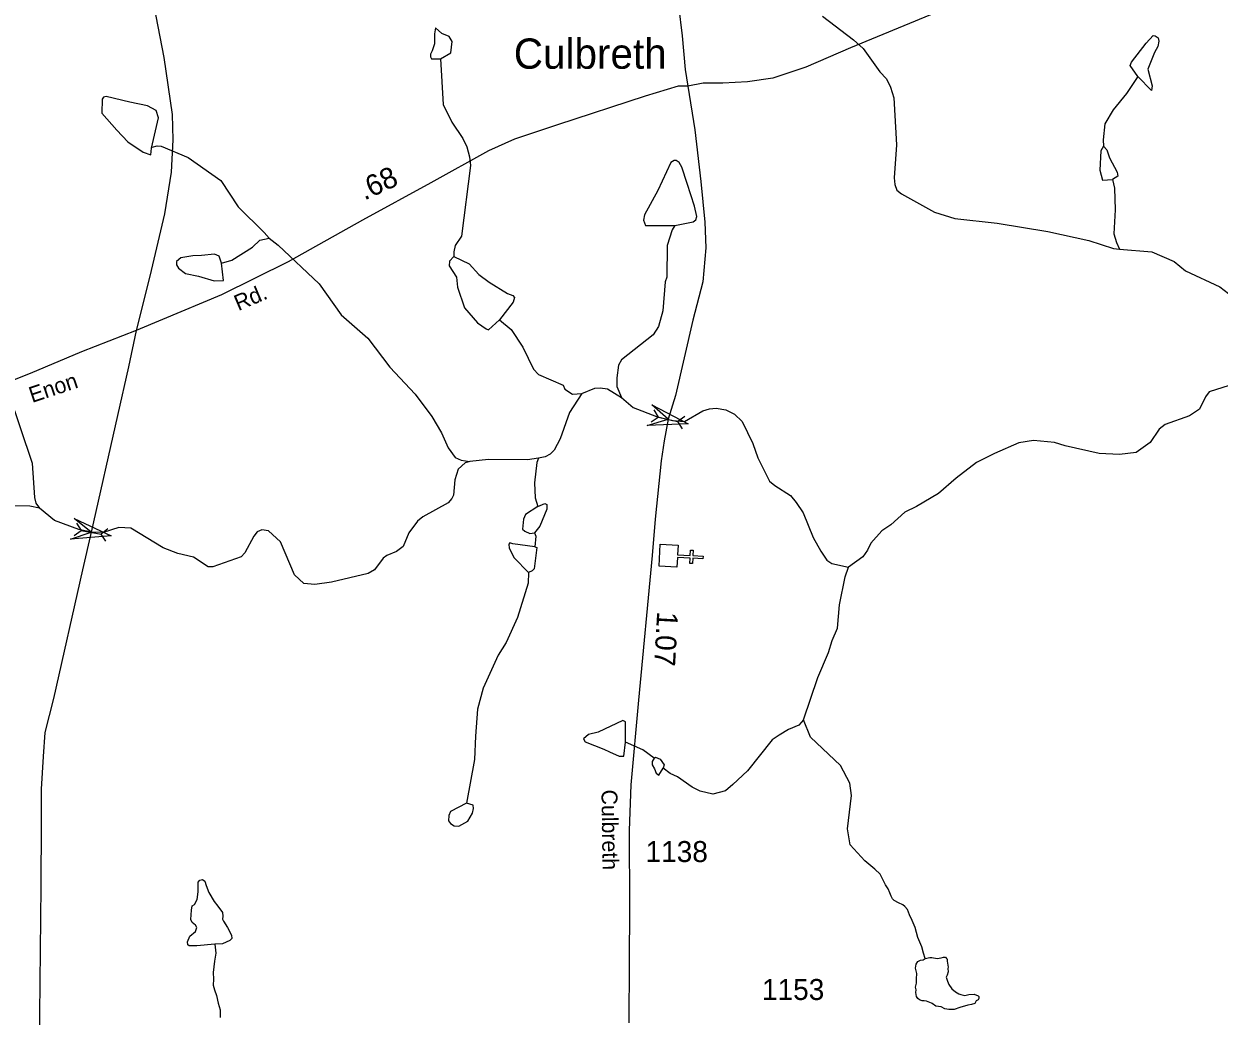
# Model space of a CAD drawing. Extents: x 2056842 to 2160602, y 826753 to 1016856.
# Drawn here: x 2076563 to 2083693, y 909292 to 915209 of the extents above; entities that cross this region are included whole.
import ezdxf

# ---------------------------------------------------------------- set-up
doc = ezdxf.new("R2010")
doc.units = 0
for name, color, linetype in [('Exist Civil Demographics City Label', 7, 'Continuous'), ('Exist Cultural Church CELL', 7, 'Continuous'), ('Exist Hydrographic Creek Single Shore', 7, 'Continuous'), ('Exist Hydrographic Misc Water Feature', 7, 'Continuous'), ('Exist Road Secondary Mileage Hundredths English Label', 7, 'Continuous'), ('Exist Road Secondary Structure Pipe Attributed CELL', 7, 'Continuous'), ('Exist Road Secondary Structure Pipe CELL', 7, 'Continuous'), ('Exist Road Secondary Structure Standard Bridge Attributed CELL', 7, 'Continuous'), ('Exist Road Secondary Type 51 Attributed', 7, 'Continuous'), ('Exist Road Secondary Type 51 Label', 7, 'Continuous'), ('Exist Road Secondary Type 51 Number Label', 7, 'Continuous')]:
    doc.layers.add(name, color=color, linetype=linetype)

msp = doc.modelspace()

# ---------------------------------------------------------------- linework, layer by layer
at = {"layer": 'Exist Cultural Church CELL'}
msp.add_lwpolyline([(2080465.2, 912100.6), (2080462, 912043.7), (2080538.1, 912039.4), (2080539.9, 912071.3), (2080555.8, 912070.4), (2080554, 912038.5), (2080614, 912035.1), (2080613.1, 912019.1), (2080553.1, 912022.5), (2080551.3, 911990.5), (2080535.3, 911991.4), (2080537.1, 912023.4), (2080461.1, 912027.7), (2080457.7, 911970.2), (2080351.4, 911976.2), (2080358.9, 912106.6)], close=True, dxfattribs=at)
at = {"layer": 'Exist Hydrographic Creek Single Shore'}
for points in [[(2081327.5, 915255.7), (2081512, 915114.1), (2081568.3, 915062.4), (2081668.8, 914922.8), (2081708.9, 914881), (2081732.9, 914832.9), (2081751.2, 914768.9), (2081768.1, 914488.9), (2081754.8, 914291), (2081758.9, 914250.9), (2081771, 914217.2), (2081797.1, 914195), (2081995.3, 914085.9), (2082115.3, 914048.3), (2082369.3, 914021), (2082671.5, 913971.8), (2082915.8, 913916.9), (2083061.8, 913869.2), (2083097.8, 913865.2)], [(2079046.9, 915000.5), (2079063.7, 914728.6), (2079116.2, 914622.8), (2079180.3, 914525), (2079204.5, 914477), (2079220.7, 914417.2), (2079226.9, 914365.2), (2079172.1, 913943), (2079134.4, 913886.9), (2079126.4, 913850.9), (2079126.6, 913822.9)], [(2077327.9, 914474.5), (2077356.6, 914481.2), (2077380.5, 914481), (2077542.5, 914411.7), (2077736.9, 914276.1), (2077841.6, 914118.8), (2077995.9, 913965.3), (2078026.1, 913931.2)], [(2078026.1, 913931.2), (2078080.3, 913889.4), (2078324.9, 913658.2), (2078455.6, 913474.7), (2078613.9, 913335.3), (2078746.4, 913161.6), (2078897, 913001.9), (2078995.3, 912868.3), (2079053.7, 912770.6), (2079094.1, 912680.5), (2079136.2, 912622.9), (2079170.4, 912606.8), (2079222.4, 912599.1)], [(2083097.8, 913865.2), (2083292.1, 913850), (2083424.1, 913792.5), (2083492.2, 913736.6), (2083696.6, 913641.1), (2083748.6, 913601.3), (2083768.8, 913515.3), (2083759.1, 913473.5), (2083767.3, 913443.5), (2083815.3, 913401.4), (2083863.5, 913381.7), (2083879.3, 913383.7), (2083919.2, 913440), (2083923.1, 913472.1), (2083937, 913494.1), (2083951, 913504)], [(2079126.6, 913822.9), (2079100.6, 913794.8), (2079098.7, 913766.8), (2079143, 913699), (2079149.2, 913638.9), (2079191.4, 913515.1), (2079267.9, 913427.4), (2079320, 913391.5), (2079333.9, 913385.5), (2079399.8, 913443.8)], [(2079126.6, 913822.9), (2079218.7, 913779.1), (2079276.9, 913715.4), (2079339.1, 913669.5)], [(2079339.1, 913669.5), (2079447.1, 913602), (2079479.1, 913590), (2079489.4, 913578.1), (2079481.4, 913550), (2079399.8, 913443.8)], [(2079399.8, 913443.8), (2079469.9, 913385.9), (2079538.2, 913282.2), (2079602.6, 913150.4), (2079632.7, 913118.6), (2079778.9, 913055), (2079788.9, 913031), (2079835.1, 913001.2), (2079891.1, 913005.4)], [(2075594.1, 913381.4), (2075654.3, 913311.9), (2075716.4, 913282.1), (2075836.3, 913256.3), (2075970.5, 913242.7), (2076108.7, 913213.2), (2076294.8, 913151.6), (2076403, 913086), (2076471.3, 913008.2), (2076612.6, 912588.9), (2076625.1, 912384.8), (2076633.3, 912350.9), (2076655.3, 912320.9)], [(2079891, 913005.3), (2079817.4, 912891), (2079761.7, 912734.6), (2079726.1, 912666.8), (2079702, 912642.7), (2079672.1, 912626.6), (2079632.3, 912618.5)], [(2079891, 913005.3), (2079968.8, 913037.5), (2080000.9, 913039.4), (2080044.8, 913033.6), (2080127.1, 912982)], [(2083752.3, 913053.3), (2083632.4, 913015.1), (2083610.5, 912985), (2083574.8, 912911), (2083515, 912872.8), (2083371.1, 912820.3), (2083335.1, 912792.2), (2083281.6, 912711.9), (2083197.7, 912653.6), (2083097.7, 912641.3), (2082977.8, 912647), (2082773.6, 912692.3), (2082709.7, 912712), (2082585.6, 912725.7), (2082497.7, 912711.4), (2082351.7, 912646.9), (2082245.9, 912592.6), (2082124.2, 912500.3), (2082018.6, 912408), (2081886.8, 912331.7), (2081816.8, 912297.3), (2081735.2, 912220.9), (2081681.3, 912185), (2081615.5, 912112.8), (2081595.6, 912070.6), (2081567.8, 912030.5), (2081481.9, 911968.3)], [(2080127.1, 912982), (2080197, 912922.2), (2080337.3, 912868.7), (2080431.4, 912844.8), (2080503.4, 912839), (2080613.3, 912901.4), (2080653.3, 912913.7), (2080693.1, 912917.8), (2080749.3, 912907.8), (2080801.3, 912882.1), (2080847.3, 912838.2), (2080911.8, 912706.6), (2080939.9, 912620.7), (2081010.5, 912482.7), (2081042.5, 912456.8), (2081134.8, 912397.1), (2081169, 912355.4), (2081211, 912293.5), (2081271.6, 912145.6), (2081315.9, 912063.9), (2081351.9, 912012), (2081382, 911992), (2081481.9, 911968.3)], [(2079222.4, 912599.1), (2079194.3, 912590.9), (2079152.5, 912553), (2079132.5, 912490.7), (2079125, 912398.7), (2079115.1, 912378.9), (2079092.9, 912352.8), (2078943.2, 912270.2), (2078911.5, 912244), (2078859.5, 912173.8), (2078826, 912091.8), (2078786, 912061.8), (2078728.1, 912039.4), (2078706.1, 912023.5), (2078654.5, 911953.3), (2078616.3, 911931.1), (2078396.7, 911880.6), (2078298.6, 911866.2), (2078232.8, 911872.1), (2078176.4, 911923.8), (2078093.9, 912119.5), (2078021.7, 912185.3), (2077981.5, 912191), (2077953.7, 912179.1), (2077933.8, 912154.9), (2077880.2, 912055), (2077858.1, 912030.8), (2077690.5, 911970.3), (2077662.3, 911972.2), (2077574.2, 912029.8), (2077480.2, 912051.5), (2077393.9, 912085.4), (2077200.1, 912202), (2077128.7, 912206.1), (2077035.8, 912176.4), (2076963.1, 912177.8), (2076889.9, 912193.6), (2076745.6, 912247.1), (2076655.3, 912320.9)], [(2079632.3, 912618.5), (2079566.1, 912610.1), (2079334.2, 912611.6), (2079222.4, 912599.1)], [(2076655.3, 912320.9), (2076597.4, 912332.9), (2076445.2, 912334.4), (2076309.4, 912286), (2076197.7, 912215.5), (2076167.8, 912183.3), (2076110.1, 912073.3), (2076096.3, 912029.3), (2076084.6, 911969.1), (2076082.9, 911857.3), (2076063, 911797), (2076043.1, 911773.1), (2076011.3, 911755.1), (2075875.4, 911720.5), (2075845.4, 911698.4)], [(2081213, 911059.6), (2081298.3, 911311.9), (2081361.9, 911460.1), (2081383.6, 911532.2), (2081415.4, 911606.2), (2081428.9, 911744.3), (2081462.4, 911912.3), (2081482.3, 911968.4)], [(2081213, 911059.6), (2081185.1, 911027.6), (2081123.4, 911001.4), (2081067.4, 910967.3), (2081025.4, 910939.1), (2080880, 910754.6), (2080792.3, 910672.4), (2080748.4, 910636.2), (2080672.5, 910616), (2080596.4, 910633.7), (2080548.5, 910657.6), (2080462.1, 910719.3), (2080418.2, 910739.1), (2080376, 910771)], [(2081701.9, 910074.5), (2081670.3, 910138.6), (2081639.1, 910168.9), (2081579.7, 910216.9), (2081491.5, 910312.6), (2081475.1, 910408.6), (2081500.5, 910606.6), (2081490.3, 910680.6), (2081433.9, 910786.4), (2081255.5, 910955.8), (2081213, 911059.6)], [(2081939.1, 909635.3), (2081928.9, 909667.2), (2081919, 909705.3), (2081894.6, 909761.1), (2081878.6, 909821.1), (2081862.4, 909861), (2081846.4, 909894.9), (2081834.1, 909926.9), (2081818.1, 909944.9), (2081806, 909954.8), (2081780, 909966.8), (2081754.2, 909980.6), (2081744.1, 909990.7), (2081735.9, 910006.6), (2081727.9, 910026.6), (2081717.9, 910050.6), (2081709.9, 910062.6), (2081701.9, 910074.5)]]:
    msp.add_lwpolyline(points, dxfattribs=at)
at = {"layer": 'Exist Hydrographic Misc Water Feature'}
for p, q in [((2079629.2, 912330.5), (2079555.4, 912284.3)), ((2079609.9, 912090.5), (2079479.9, 912108.1))]:
    msp.add_line(p, q, dxfattribs=at)
for points in [[(2079116.4, 915104.8), (2079098.5, 915134.7), (2079056.3, 915152.6), (2079018.2, 915186.4), (2079012.4, 915150.4), (2079012.6, 915090.4)], [(2083258.2, 915093.9), (2083300, 915140), (2083312.1, 915138), (2083328.1, 915126), (2083332.2, 915106), (2083326.1, 915074), (2083306.4, 915038.1)], [(2079012.6, 915090.4), (2078998.7, 915048.4), (2078988.6, 915028.4), (2078988.8, 915012.4), (2078994.8, 915000.4), (2079046.9, 915000.5)], [(2079046.9, 915000.5), (2079108.8, 915036.7), (2079116.4, 915104.8)], [(2083206.8, 914895.6), (2083162.5, 914961.6), (2083170.5, 914981.6), (2083258.2, 915093.9)], [(2083306.4, 915038.1), (2083266.6, 914939.8), (2083292.9, 914840), (2083289, 914812), (2083206.8, 914895.6)], [(2083206.8, 914895.6), (2083141.1, 914793.5), (2083061.4, 914697.3), (2083011.7, 914613.1), (2083000.1, 914517), (2083002.1, 914481.1)], [(2077193.8, 914742.7), (2077053.8, 914776.2), (2077037.8, 914772.2), (2077029.8, 914760.2), (2077028.1, 914676.1), (2077116.3, 914576.5)], [(2077322.8, 914469.1), (2077366, 914649.3), (2077351.9, 914693.2), (2077299.8, 914721), (2077193.8, 914742.7)], [(2077116.3, 914576.5), (2077182.5, 914506.7), (2077274.8, 914444.9), (2077318.9, 914429), (2077322.8, 914469.1)], [(2083002.1, 914481.1), (2082986.1, 914453), (2082980.6, 914337.1)], [(2083002.1, 914481.1), (2083022.2, 914459.2), (2083038.4, 914411.2), (2083084.5, 914325.4), (2083088.6, 914301.4), (2083056.9, 914281.3)], [(2080519.1, 914257.3), (2080486.7, 914355.1), (2080470.7, 914383.1), (2080454.5, 914395), (2080442.6, 914395), (2080422.8, 914382.9), (2080345.2, 914216.7)], [(2082980.6, 914337.1), (2082996.8, 914277.1), (2083056.9, 914281.3)], [(2083056.9, 914281.3), (2083069, 914229.3), (2083073.3, 914101.4), (2083063.8, 913957.3), (2083080, 913905.3), (2083098.1, 913865.5)], [(2080345.2, 914216.7), (2080265.7, 914070.4), (2080259.7, 914038.4), (2080269.8, 914006.5), (2080445.7, 914007.1)], [(2080445.7, 914007.1), (2080555.8, 914029.4), (2080571.6, 914041.5), (2080577.8, 914061.5), (2080563.4, 914121.4), (2080519.1, 914257.3)], [(2080445.7, 914007.1), (2080429.9, 913981), (2080400.2, 913886.9), (2080398.8, 913698.9), (2080388.9, 913670.9), (2080373.5, 913498.8), (2080347.9, 913404.7), (2080315.9, 913354.7), (2080128.5, 913206), (2080110.5, 913174), (2080098.8, 913098), (2080099, 913046), (2080127.1, 912982.1)], [(2077740.9, 913782.5), (2077802.8, 913800.7), (2077926.5, 913877), (2077970.3, 913919.2), (2078026.3, 913931.4)], [(2077570.7, 913826), (2077498.7, 913813.7), (2077472.9, 913791.6), (2077472.9, 913771.7), (2077485, 913751.7), (2077527, 913719.8), (2077605.1, 913704)], [(2077740.9, 913782.5), (2077726.7, 913824.5), (2077698.6, 913836.3), (2077622.8, 913828.1), (2077570.7, 913826)], [(2077605.1, 913704), (2077697, 913676.3), (2077753.2, 913678.6), (2077740.9, 913782.5)], [(2079632.3, 912618.5), (2079622.4, 912594.5), (2079608.9, 912472.4), (2079613, 912382.5), (2079629.2, 912330.5)], [(2079629.2, 912330.5), (2079669.2, 912348.7), (2079681.3, 912342.7), (2079681.3, 912314.8), (2079639.7, 912214.6), (2079607.7, 912174.5)], [(2079555.4, 912284.3), (2079543.5, 912256.3), (2079537.8, 912196.3), (2079551.7, 912184.3), (2079579.8, 912170.4), (2079607.7, 912174.5)], [(2079607.7, 912174.5), (2079615.9, 912154.5), (2079609.9, 912090.5)], [(2079479.9, 912108.1), (2079461.9, 912114), (2079455.9, 912106), (2079458, 912082), (2079486.3, 912024.2), (2079572.4, 911938.4)], [(2079609.9, 912090.5), (2079622, 912086.5), (2079606.2, 911958.6), (2079594.6, 911946.5), (2079572.4, 911938.4)], [(2079572.4, 911938.4), (2079570.8, 911874.4), (2079507.4, 911668.2), (2079439.9, 911520.1), (2079392.2, 911443.9), (2079302.8, 911247.6), (2079269.1, 911121.6), (2079255.6, 910961.4), (2079250.1, 910821.5), (2079202.9, 910561.4)], [(2080151.7, 910926.3), (2080151.3, 911046.3), (2080135.3, 911054.3), (2079987.4, 910985.8)], [(2079987.4, 910985.8), (2079931.5, 910971.6), (2079901.5, 910945.5), (2079911.6, 910927.5), (2080021.7, 910883.9)], [(2080021.7, 910883.9), (2080055.9, 910868), (2080113.7, 910842.2), (2080141.8, 910842.3), (2080151.7, 910926.3)], [(2080321.9, 910830.8), (2080255.6, 910880.6), (2080151.7, 910926.3)], [(2080321.9, 910830.8), (2080310, 910810.8), (2080310.2, 910790.8), (2080324.1, 910766.9)], [(2080321.9, 910830.8), (2080329.9, 910836.9), (2080358, 910825), (2080382, 910791), (2080376, 910771)], [(2080324.1, 910766.9), (2080334.2, 910740.9), (2080350.2, 910729), (2080376, 910771)], [(2079202.9, 910561.4), (2079106.9, 910513), (2079097.1, 910489)], [(2079211.3, 910455.3), (2079239.2, 910501.5), (2079244.9, 910529.5), (2079242.9, 910549.5), (2079202.9, 910561.4)], [(2079097.1, 910489), (2079095.3, 910457), (2079107.1, 910441), (2079129.3, 910427.1), (2079157.4, 910425.2), (2079211.3, 910455.3)], [(2077701.5, 909721.4), (2077594.2, 909711.4), (2077549.3, 909710.1), (2077540.6, 909717.6), (2077539.3, 909733.9), (2077553.1, 909767.6), (2077585.5, 909796.3), (2077594.2, 909821.2), (2077586.7, 909835), (2077566.8, 909849.9), (2077559.3, 909868.7), (2077563, 909923.6), (2077566.8, 909948.5), (2077579.3, 909957.3), (2077595.5, 909987.2), (2077603, 910032.2), (2077601.7, 910090.8), (2077611.7, 910103.3), (2077627.9, 910105.8), (2077642.9, 910097.1), (2077650.4, 910070.8), (2077666.6, 910029.7), (2077697.8, 909974.7), (2077720.2, 909947.3), (2077746.4, 909909.8), (2077750.2, 909887.4), (2077747.7, 909869.9), (2077753.9, 909857.4), (2077777.6, 909820), (2077801.3, 909775), (2077802.6, 909753.8), (2077791.3, 909742.6), (2077747.7, 909722.6), (2077701.5, 909721.4)], [(2077701.5, 909721.4), (2077707.5, 909666.2), (2077699.7, 909620.1), (2077691.7, 909552.1), (2077693.9, 909512.1), (2077692.1, 909476.1), (2077700.1, 909448.1), (2077712.2, 909414.2), (2077722.4, 909368.3), (2077732.5, 909328.2), (2077732.7, 909284.2)], [(2081939.1, 909635.3), (2081967, 909641.4), (2081979.1, 909641.4), (2082011.1, 909635.4), (2082035.1, 909639.6), (2082049, 909643.6), (2082061.1, 909643.6), (2082067.1, 909635.6), (2082071.2, 909631.6), (2082071.2, 909619.7), (2082073.2, 909607.7), (2082077.1, 909583.8), (2082073.4, 909575.8), (2082075.3, 909555.7), (2082069.5, 909535.7), (2082063.4, 909523.7), (2082071.6, 909499.7), (2082079.6, 909479.7), (2082097.6, 909453.8), (2082119.8, 909435.8), (2082139.7, 909423.9), (2082151.8, 909419.9), (2082175.7, 909414.1), (2082199.7, 909420.1), (2082231.7, 909422.2), (2082255.9, 909412.2), (2082259.8, 909408.2), (2082259.8, 909396.2), (2082255.9, 909388.3), (2082243.8, 909382.2), (2082236, 909366.2), (2082215.9, 909360.2), (2082194, 909356.1), (2082146, 909344), (2082112.2, 909331.9), (2082080, 909331.8), (2082056, 909335.7), (2082034.1, 909347.5), (2082001.9, 909351.4), (2081979.9, 909367.4), (2081976, 909369.4), (2081947.9, 909381.4), (2081934, 909383.3), (2081921.9, 909383.2), (2081905.9, 909389.2), (2081895.9, 909397.2), (2081887.9, 909409.2), (2081883.8, 909433.1), (2081885.8, 909449.1), (2081881.7, 909465.1), (2081887.7, 909489.1), (2081887.4, 909513.1), (2081889.5, 909545.1), (2081881.3, 909577.1), (2081885.2, 909601.1), (2081895.2, 909617.2), (2081911.2, 909625.2), (2081927, 909627.2), (2081939.1, 909635.3)]]:
    msp.add_lwpolyline(points, dxfattribs=at)
at = {"layer": 'Exist Road Secondary Structure Pipe Attributed CELL'}
msp.add_lwpolyline([(2080308.1, 912937.6), (2080524.3, 912824.8), (2080280.7, 912814.4), (2080405.3, 912851.3)], close=True, dxfattribs=at)
at = {"layer": 'Exist Road Secondary Structure Pipe CELL'}
for p, q in [((2080304.2, 912835.6), (2080346.2, 912864.2)), ((2080319.9, 912907.6), (2080346.2, 912864.2)), ((2080346.2, 912864.2), (2080464.4, 912838.4)), ((2080506.3, 912867), (2080464.4, 912838.4)), ((2080490.6, 912795), (2080464.4, 912838.4)), ((2076875.7, 912230.8), (2076903.6, 912188.4)), ((2076862.8, 912158.3), (2076903.6, 912188.4)), ((2076903.6, 912188.4), (2077022.7, 912167.1)), ((2077063.5, 912197.3), (2077022.7, 912167.1)), ((2077050.5, 912124.7), (2077022.7, 912167.1))]:
    msp.add_line(p, q, dxfattribs=at)
at = {"layer": 'Exist Road Secondary Structure Standard Bridge Attributed CELL'}
msp.add_lwpolyline([(2076862.2, 912259.6), (2077083.2, 912156.6), (2076840.3, 912135.3), (2076963.1, 912177.8)], close=True, dxfattribs=at)
at = {"layer": 'Exist Road Secondary Type 51 Attributed'}
for points in [[(2076745.4, 918632.8), (2076756.2, 918474.7), (2076811, 918112.6), (2076882.8, 917738.9), (2077048.9, 916868.3), (2077220.4, 915925.8), (2077397.3, 915008.5), (2077446.6, 914669.8), (2077450.2, 914517), (2077441.3, 914324.8), (2077401.7, 914076.8), (2077312.9, 913704), (2077231.6, 913381)], [(2079956.5, 918619.8), (2079981.6, 918443.7), (2080020.2, 918218.2), (2080045.4, 918097.8), (2080101, 917945.1), (2080183.6, 917738.5), (2080263.5, 917521.9), (2080295.8, 917380), (2080321, 917155.4), (2080397.3, 916629.8), (2080426, 916371), (2080468.2, 915922.7), (2080466.4, 915606.5), (2080467.3, 915318.1), (2080488.9, 915138.4), (2080506.8, 914937.1), (2080523, 914838.3)], [(2086548.2, 916438.4), (2086273.5, 916316.2), (2085832.7, 916112.3), (2085126.1, 915820.3), (2084874.7, 915703.5), (2084596.4, 915608.3), (2084286.6, 915533.7), (2084013.7, 915483.4), (2083814.4, 915470.8), (2083409.5, 915531), (2083053.9, 915579.5), (2082842.1, 915579.5), (2082723.5, 915557.9), (2082618.5, 915521.1), (2082289.9, 915397.1), (2081493.5, 915067.4), (2081227.8, 914950.6), (2081030.3, 914885.9), (2080879.4, 914864.3), (2080732.2, 914855.4), (2080615.5, 914855.4), (2080523, 914838.3)], [(2080523, 914838.3), (2080466.4, 914837.4), (2080268.9, 914778.1), (2079746.4, 914607.4), (2079488.7, 914522), (2079334.3, 914452), (2078989.5, 914261.5), (2078582.8, 914039.6), (2078139.3, 913789.8), (2077740.7, 913593.9), (2077389.6, 913445.7), (2077231.6, 913381)], [(2080523, 914838.3), (2080564.5, 914577.1), (2080600.4, 914269.7), (2080624.7, 914026.1), (2080630.1, 913873.3), (2080612.1, 913672), (2080552.8, 913441.9), (2080450.4, 912993.2), (2080405.3, 912851.3), (2080381.3, 912722), (2080364.2, 912602.5), (2080328.3, 912255.5), (2080310.3, 912039.8), (2080228.6, 911176.1), (2080182.8, 910671.9), (2080173.8, 910398.7), (2080174.7, 909941.2), (2080172.9, 909608.6), (2080171.1, 909251.9)], [(2077231.6, 913381), (2076906.2, 913253.2), (2076599.1, 913123.7), (2076366.4, 913033), (2076154.5, 912910.7), (2075933.5, 912734.6), (2075739.5, 912562), (2075126.1, 912025.4), (2074615.1, 911580.5), (2074336.6, 911323.5), (2074162.4, 911185.1), (2074014.2, 911065.5), (2073757.3, 910939.7), (2073479.4, 910823.8), (2073193.3, 910686.3), (2072938.1, 910572.8), (2072682.2, 910458.9), (2072202.6, 910237.8), (2071745.5, 910024.8), (2071402.4, 909873.8), (2071145.5, 909765.9), (2070797.9, 909700.3), (2070209.2, 909609)], [(2077231.6, 913381), (2077185.6, 913164.2), (2077120.9, 912873), (2076963.1, 912177.8)], [(2076963.1, 912177.8), (2076911.7, 911953.5), (2076738.3, 911185.1), (2076688, 910983.7), (2076677.3, 910839.9), (2076666.5, 910645.8), (2076666.5, 910440.9), (2076663.8, 910064.3), (2076656.6, 909302.1), (2076648.5, 908742.2), (2076644, 907831.7), (2076633.2, 907109.1), (2076627, 906497), (2076618.9, 905744.8), (2076613.5, 905417.6), (2076612.6, 904577.2), (2076600.9, 903785.4), (2076592.8, 903013.4), (2076581.2, 902257.5), (2076567.7, 901568.1)]]:
    msp.add_lwpolyline(points, dxfattribs=at)

# ---------------------------------------------------------------- texts
at = {"layer": 'Exist Civil Demographics City Label'}
msp.add_text('Culbreth', height=180.45, dxfattribs=at).set_placement((2079485, 914942))
at = {"layer": 'Exist Road Secondary Mileage Hundredths English Label'}
for s, rotation, p in [('.68', 24.65311, (2078593.8, 914154.9)), ('1.07', 266.73441, (2080340.5, 911706.6))]:
    msp.add_text(s, height=125, rotation=rotation, dxfattribs=at).set_placement(p)
at = {"layer": 'Exist Road Secondary Type 51 Label'}
for s, rotation, p in [('Rd.', 23.02819, (2077841.7, 913496)), ('Enon', 18.41049, (2076611.3, 912948.1)), ('Culbreth', 270.82733, (2080007.8, 910642.2))]:
    msp.add_text(s, height=95, rotation=rotation, dxfattribs=at).set_placement(p)
at = {"layer": 'Exist Road Secondary Type 51 Number Label'}
for s, p in [('1138', (2080271, 910210.7)), ('1153', (2080965.5, 909388))]:
    msp.add_text(s, height=125, dxfattribs=at).set_placement(p)

doc.saveas('drawing.dxf')
